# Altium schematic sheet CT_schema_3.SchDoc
size 199 x 169 mm
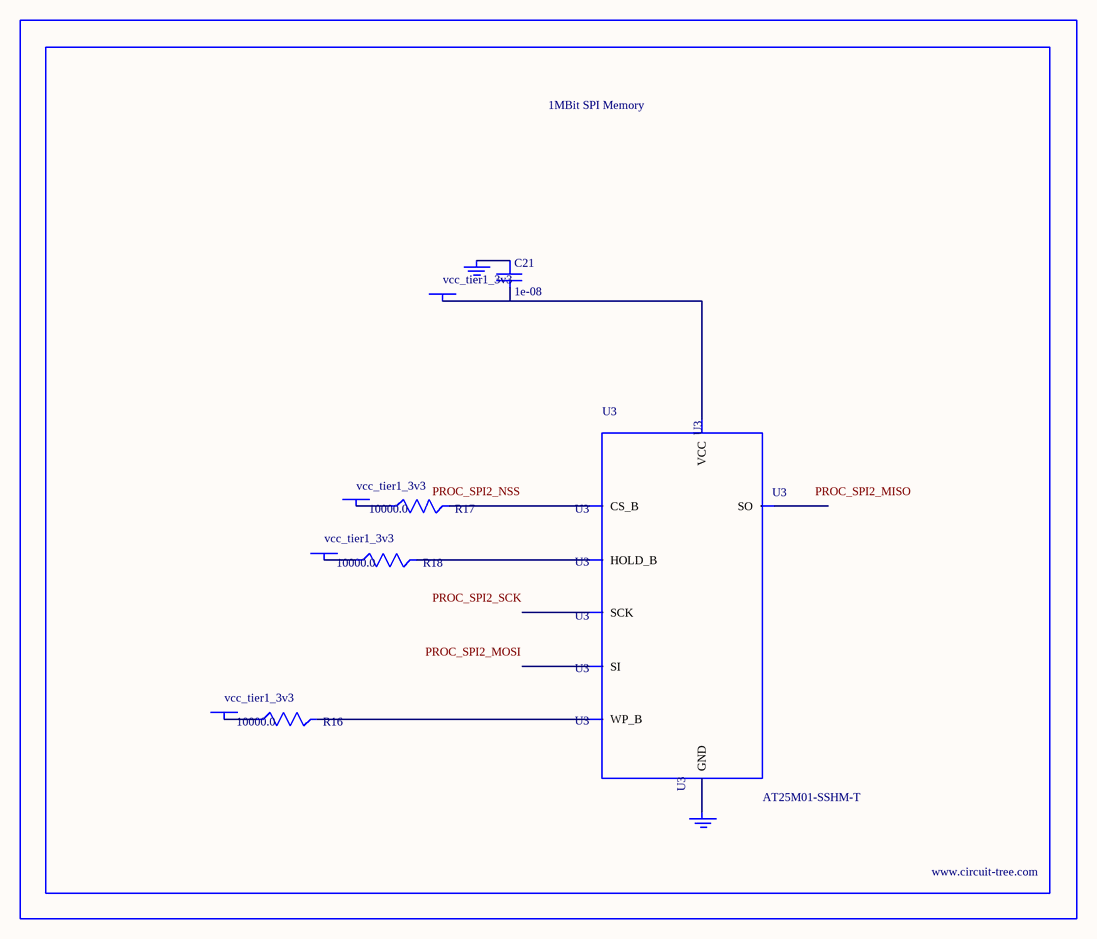
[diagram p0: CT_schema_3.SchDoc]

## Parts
BORDER2  (no value)
C21  1e-08  [C0402]
GND_INSTANCE_2_0  (no value)
GND_INSTANCE_2_1  (no value)
POWER_INSTANCE_2_0  vcc_tier1_3v3
POWER_INSTANCE_2_1  vcc_tier1_3v3
POWER_INSTANCE_2_2  vcc_tier1_3v3
POWER_INSTANCE_2_3  vcc_tier1_3v3
R16  10000.0  [R0603]
R17  10000.0  [R0603]
R18  10000.0  [R0603]
U3  AT25M01-SSHM-T  [SOIC-8]

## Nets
NetC21_1: C21.1 GND_INSTANCE_2_0.0(GND)
NetC21_2: C21.2 POWER_INSTANCE_2_3.0(PWR) U3.8(VCC)
NetGND_INSTANCE_2_1_0: GND_INSTANCE_2_1.0(GND) U3.4(GND)
NetPOWER_INSTANCE_2_0_0: POWER_INSTANCE_2_0.0(PWR) R17.1
NetPOWER_INSTANCE_2_1_0: POWER_INSTANCE_2_1.0(PWR) R16.1
NetPOWER_INSTANCE_2_2_0: POWER_INSTANCE_2_2.0(PWR) R18.1
NetR16_2: R16.2 U3.3(WP_B)
NetR17_2: R17.2 U3.1(CS_B)
NetR18_2: R18.2 U3.7(HOLD_B)

Not connected (* = marked no-connect by the designer): U3 2(SO) 5(SI) 6(SCK)

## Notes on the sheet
- Labels drawn without touching a wire or pin: PROC_SPI2_MISO, PROC_SPI2_MOSI, PROC_SPI2_NSS, PROC_SPI2_SCK

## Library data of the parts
BORDER2 = BORDER_PAGE2
C21 = C0402C103K3RAC
GND_INSTANCE_2_0 GND_INSTANCE_2_1 = GND
POWER_INSTANCE_2_0-POWER_INSTANCE_2_3 = PWR
R16-R18 = RC0603JR-0710KL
